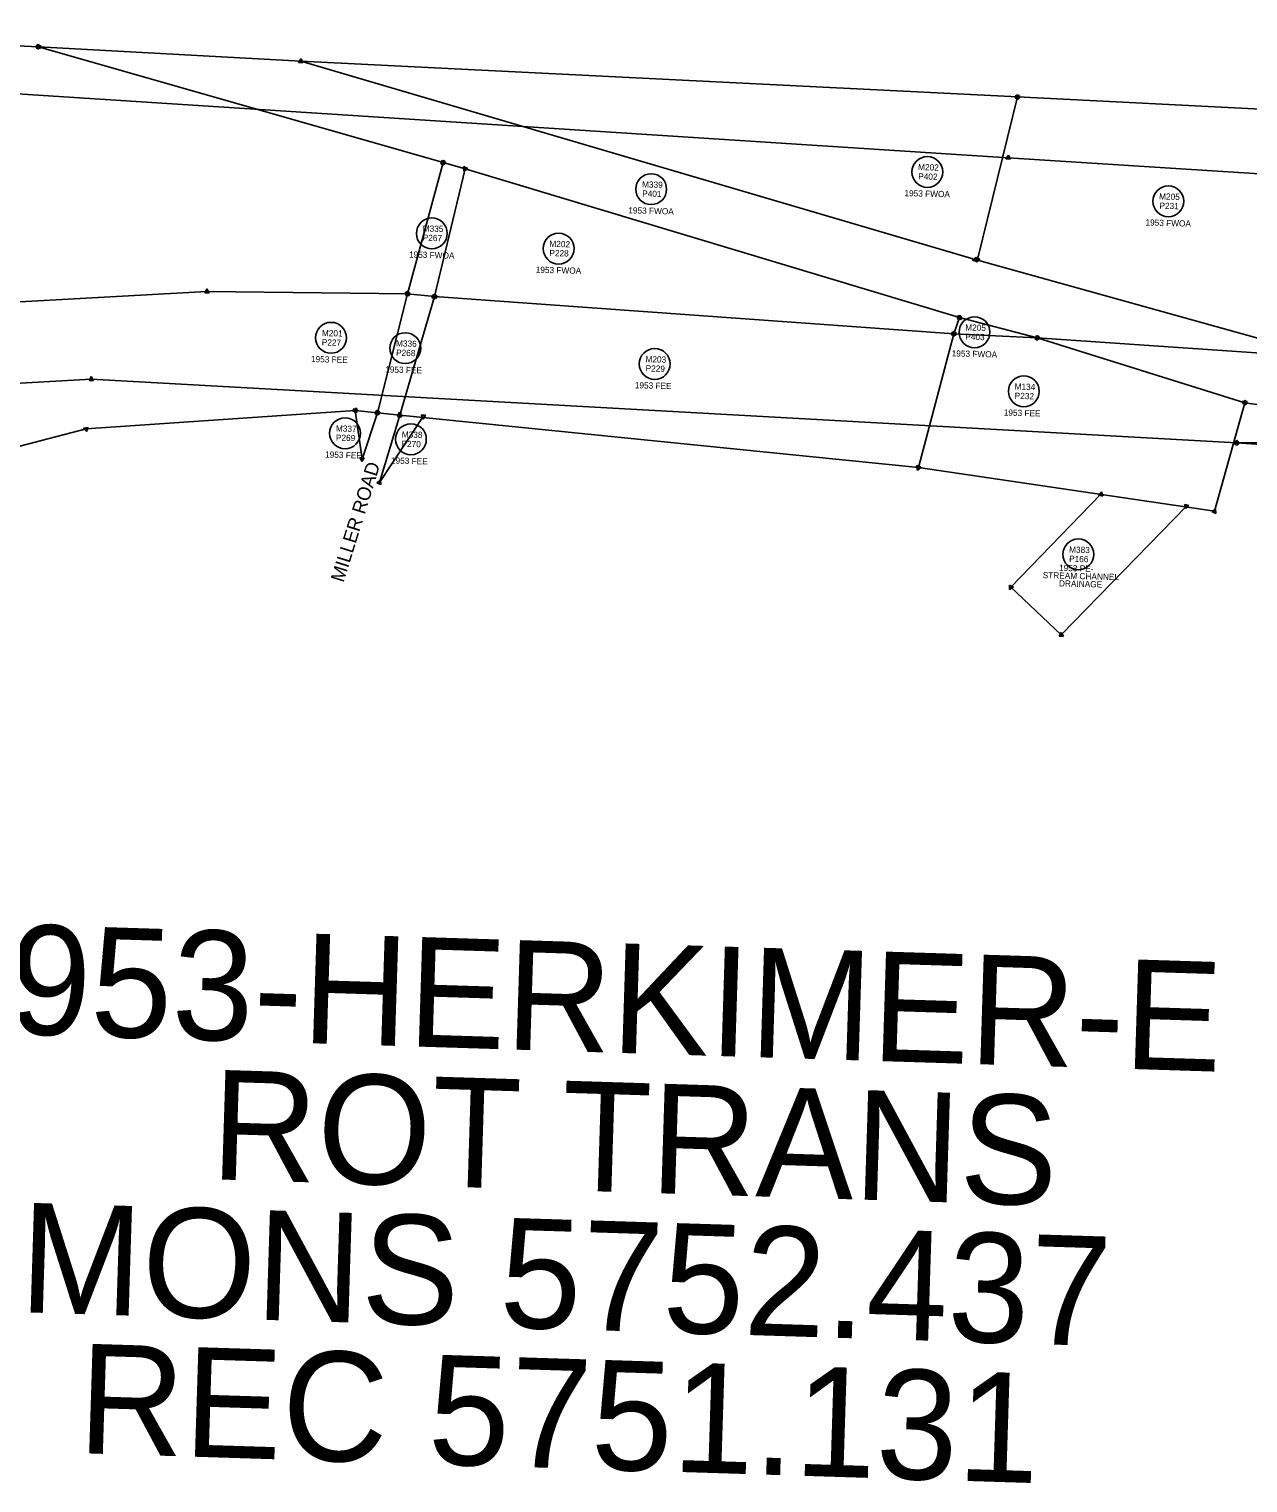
# Model space of a CAD drawing. Extents: x 325018 to 414989, y 1517547 to 1550415.
# Drawn here: x 374498 to 375532, y 1522317 to 1523550 of the extents above; entities that cross this region are included whole.
import ezdxf

# ---------------------------------------------------------------- set-up
doc = ezdxf.new("R2010")
doc.units = 0
for name, color, linetype in [('LAM_I', 7, 'Continuous'), ('Level 56', 7, 'Continuous'), ('MEE', 7, 'Continuous'), ('MHB', 7, 'Continuous'), ('MHBWOA', 7, 'Continuous'), ('MRBL1', 7, 'Continuous'), ('MRBL2', 7, 'Continuous'), ('S_C', 7, 'Continuous')]:
    doc.layers.add(name, color=color, linetype=linetype)

msp = doc.modelspace()

# ---------------------------------------------------------------- linework, layer by layer
at = {"layer": 'Level 56'}
for centre in [(375260.2, 1523429.2), (375025.8, 1523414.6), (375464.8, 1523404.3), (374839.6, 1523377.1), (374947.2, 1523364.2), (374754, 1523288.5), (375300.2, 1523293.2), (374817, 1523279.7), (375028.8, 1523266.3), (375342.1, 1523243.1), (374765.9, 1523207.5), (374821.8, 1523202.4), (375388.4, 1523104.7)]:
    msp.add_circle(centre, 13.1, dxfattribs=at)
at = {"layer": 'MEE'}
for p, q in [((375407.6, 1523155.7), (375331.1, 1523076.8)), ((375373.9, 1523036.3), (375480.1, 1523145.6)), ((375331.1, 1523076.8), (375373.9, 1523036.3))]:
    msp.add_line(p, q, dxfattribs=at)
for points in [[(375405.5, 1523155.1), (375408.1, 1523157.8)], [(375409.1, 1523154.1), (375405.5, 1523155.1)], [(375408.1, 1523157.8), (375409.1, 1523154.1)], [(375479.6, 1523143.5), (375478.6, 1523147.1)], [(375478.6, 1523147.1), (375482.2, 1523146.2)], [(375482.2, 1523146.2), (375479.6, 1523143.5)], [(375329.9, 1523078.6), (375333.2, 1523076.8)], [(375330, 1523074.9), (375329.9, 1523078.6)], [(375333.2, 1523076.8), (375330, 1523074.9)], [(375372, 1523035.2), (375373.8, 1523038.5)], [(375375.8, 1523035.3), (375372, 1523035.2)], [(375373.8, 1523038.5), (375375.8, 1523035.3)]]:
    msp.add_lwpolyline(points, dxfattribs=at)
for centre, radius in [((375407.6, 1523155.7), 1.09), ((375480.1, 1523145.6), 1.09), ((375331.1, 1523076.8), 0.227), ((375373.9, 1523036.3), 0.227)]:
    msp.add_circle(centre, radius, dxfattribs=at)
at = {"layer": 'MHB'}
for p, q in [((374489.7, 1523319), (374648.6, 1523327.8)), ((374818.8, 1523325.8), (374793.5, 1523224.9)), ((374841.7, 1523323.4), (374812.4, 1523222.8)), ((375282.6, 1523291.9), (375353.5, 1523288.4)), ((375353.5, 1523288.4), (375529.7, 1523233.4)), ((374774.5, 1523226.9), (374546, 1523211.1)), ((374793.5, 1523224.9), (374774.5, 1523226.9)), ((374780.3, 1523185.6), (374774.5, 1523226.9)), ((375529.7, 1523233.4), (375503.9, 1523141.3)), ((375529.7, 1523233.4), (375838.3, 1523188.6)), ((374793.5, 1523224.9), (374780.3, 1523185.6)), ((374812.4, 1523222.8), (374793.5, 1523224.9)), ((374812.4, 1523222.8), (374795.2, 1523165.7)), ((374795.2, 1523165.7), (374832.3, 1523221.7)), ((374546, 1523211.1), (374333.7, 1523156.4)), ((375835.5, 1523177.6), (375522.7, 1523199.3)), ((375503.9, 1523141.3), (375252.6, 1523178.3))]:
    msp.add_line(p, q, dxfattribs=at)
for points in [[(374646.8, 1523326.7), (374648.6, 1523330)], [(374650.5, 1523326.7), (374646.8, 1523326.7)], [(374648.6, 1523330), (374650.5, 1523326.7)], [(374816.8, 1523326.7), (374820.6, 1523327.2)], [(374819.1, 1523323.7), (374816.8, 1523326.7)], [(374816.9, 1523325), (374819.1, 1523328)], [(374820.6, 1523324.5), (374816.9, 1523325)], [(374819.1, 1523328), (374820.6, 1523324.5)], [(374820.6, 1523327.2), (374819.1, 1523323.7)], [(374839.8, 1523324.3), (374843.5, 1523324.6)], [(374841.9, 1523321.2), (374839.8, 1523324.3)], [(374843.5, 1523324.6), (374841.9, 1523321.2)], [(375280.7, 1523290.9), (375282.7, 1523294.1)], [(375284.5, 1523290.7), (375280.7, 1523290.9)], [(375282.7, 1523294.1), (375284.5, 1523290.7)], [(375351.5, 1523287.6), (375353.9, 1523290.5)], [(375353.9, 1523290.5), (375355.2, 1523287)], [(375355.2, 1523287), (375351.5, 1523287.6)], [(374772.4, 1523226.6), (374775.4, 1523229)], [(374775.9, 1523225.2), (374772.4, 1523226.6)], [(374774.5, 1523224.8), (374772.7, 1523228.1)], [(374772.7, 1523228.1), (374776.5, 1523228)], [(374776.5, 1523228), (374774.5, 1523224.8)], [(374775.4, 1523229), (374775.9, 1523225.2)], [(374791.3, 1523224.7), (374794.4, 1523226.9)], [(374793.2, 1523222.7), (374791.7, 1523226.2)], [(374791.7, 1523226.2), (374795.5, 1523225.8)], [(374791.8, 1523223.4), (374793, 1523227)], [(374793, 1523227), (374795.5, 1523224.2)], [(374794.4, 1523226.9), (374794.7, 1523223.1)], [(375527.7, 1523232.6), (375530, 1523235.6)], [(375531.4, 1523232.1), (375527.7, 1523232.6)], [(375527.8, 1523234.6), (375531.6, 1523234.5)], [(375529.6, 1523231.2), (375527.8, 1523234.6)], [(375531.6, 1523234.5), (375529.6, 1523231.2)], [(375530, 1523235.6), (375531.4, 1523232.1)], [(374794.7, 1523223.1), (374791.3, 1523224.7)], [(374795.5, 1523224.2), (374791.8, 1523223.4)], [(374795.5, 1523225.8), (374793.2, 1523222.7)], [(374810.2, 1523222.7), (374813.3, 1523224.8)], [(374813.6, 1523221), (374810.2, 1523222.7)], [(374810.8, 1523221.3), (374811.9, 1523225)], [(374814.5, 1523222.2), (374810.8, 1523221.3)], [(374811.9, 1523225), (374814.5, 1523222.2)], [(374813.3, 1523224.8), (374813.6, 1523221)], [(374832.2, 1523219.5), (374830.5, 1523222.9)], [(374830.5, 1523222.9), (374834.3, 1523222.7)], [(374834.3, 1523222.7), (374832.2, 1523219.5)], [(374543.9, 1523211.9), (374547.7, 1523212.5)], [(374546.3, 1523209), (374543.9, 1523211.9)], [(374547.7, 1523212.5), (374546.3, 1523209)], [(375522.6, 1523197.2), (375520.9, 1523200.5)], [(375520.9, 1523200.5), (375524.7, 1523200.3)], [(375524.7, 1523200.3), (375522.6, 1523197.2)], [(374780.1, 1523183.4), (374778.5, 1523186.8)], [(374778.5, 1523186.8), (374782.2, 1523186.5)], [(374782.2, 1523186.5), (374780.1, 1523183.4)], [(375252.3, 1523176.1), (375250.9, 1523179.7)], [(375250.9, 1523179.7), (375254.6, 1523179.1)], [(375254.6, 1523179.1), (375252.3, 1523176.1)], [(374793, 1523165.5), (374796.1, 1523167.7)], [(374796.4, 1523163.9), (374793, 1523165.5)], [(374796.1, 1523167.7), (374796.4, 1523163.9)], [(375501.7, 1523141.2), (375504.9, 1523143.2)], [(375505.1, 1523139.5), (375501.7, 1523141.2)], [(375504.9, 1523143.2), (375505.1, 1523139.5)]]:
    msp.add_lwpolyline(points, dxfattribs=at)
for centre, radius in [((374648.6, 1523327.8), 0.227), ((374818.9, 1523325.8), 1.09), ((374818.8, 1523325.8), 0.227), ((374841.7, 1523323.4), 0.227), ((375282.6, 1523291.9), 1.09), ((375353.5, 1523288.4), 0.227), ((374774.5, 1523226.9), 1.09), ((374774.5, 1523226.9), 0.227), ((375529.7, 1523233.4), 1.09), ((375529.7, 1523233.4), 0.227), ((374793.5, 1523224.9), 1.09), ((374793.5, 1523224.9), 1.09), ((374793.5, 1523224.9), 0.227), ((374812.4, 1523222.8), 1.09), ((374812.4, 1523222.8), 0.227), ((374832.3, 1523221.7), 1.09), ((374546, 1523211.1), 0.227), ((375522.7, 1523199.3), 1.09), ((374780.3, 1523185.6), 0.227), ((375252.6, 1523178.3), 1.09), ((374795.2, 1523165.7), 0.227), ((375503.9, 1523141.3), 0.227)]:
    msp.add_circle(centre, radius, dxfattribs=at)
at = {"layer": 'MHBWOA'}
for p, q in [((374505.7, 1523535.4), (374179, 1523550.5)), ((374505.7, 1523535.4), (374728.3, 1523523.1)), ((374849.1, 1523437.1), (374505.7, 1523535.4)), ((374728.3, 1523523.1), (375336.7, 1523492.9)), ((374728.3, 1523523.1), (375300.7, 1523354.9)), ((375336.7, 1523492.9), (375302.7, 1523354.8)), ((375336.7, 1523492.9), (375626.3, 1523478.2)), ((374849.1, 1523437.1), (374818.8, 1523325.8)), ((374867.8, 1523431.9), (374849.1, 1523437.1)), ((374841.7, 1523323.4), (374867.8, 1523431.9)), ((375287.5, 1523305.6), (374867.8, 1523431.9)), ((375300.7, 1523354.9), (375568.5, 1523280.5)), ((374648.6, 1523327.8), (374818.8, 1523325.8)), ((374818.8, 1523325.8), (374841.7, 1523323.4)), ((375282.6, 1523291.9), (374841.7, 1523323.4)), ((375287.5, 1523305.6), (375282.6, 1523291.9)), ((375353.5, 1523288.4), (375287.5, 1523305.6)), ((375252.6, 1523178.3), (375282.6, 1523291.9)), ((375602, 1523271.3), (375353.5, 1523288.4)), ((374812.4, 1523222.8), (375252.6, 1523178.3))]:
    msp.add_line(p, q, dxfattribs=at)
for points in [[(374503.7, 1523534.4), (374505.8, 1523537.6)], [(374505.3, 1523533.3), (374504, 1523536.8)], [(374504, 1523536.8), (374507.7, 1523536.2)], [(374505.1, 1523533.3), (374504.2, 1523537)], [(374504.2, 1523537), (374507.8, 1523535.9)], [(374507.8, 1523535.9), (374505.1, 1523533.3)], [(374507.7, 1523536.2), (374505.3, 1523533.3)], [(374505.8, 1523537.6), (374507.5, 1523534.2)], [(374507.5, 1523534.2), (374503.7, 1523534.4)], [(374726.3, 1523522.3), (374728.7, 1523525.2)], [(374730, 1523521.7), (374726.3, 1523522.3)], [(374726.4, 1523522.1), (374728.5, 1523525.2)], [(374728.5, 1523525.2), (374730.2, 1523521.9)], [(374728.7, 1523525.2), (374730, 1523521.7)], [(374730.2, 1523521.9), (374726.4, 1523522.1)], [(375334.7, 1523491.9), (375336.8, 1523495)], [(375334.7, 1523493.7), (375338.4, 1523494.2)], [(375336.9, 1523490.7), (375334.7, 1523493.7)], [(375338.5, 1523491.7), (375334.7, 1523491.9)], [(375336.8, 1523495), (375338.5, 1523491.7)], [(375338.4, 1523494.2), (375336.9, 1523490.7)], [(374846.9, 1523437.1), (374850.2, 1523439)], [(374850.1, 1523435.2), (374846.9, 1523437.1)], [(374847.2, 1523436.1), (374849.1, 1523439.3)], [(374851, 1523436), (374847.2, 1523436.1)], [(374848.5, 1523435), (374847.5, 1523438.7)], [(374847.5, 1523438.7), (374851.2, 1523437.7)], [(374851.2, 1523437.7), (374848.5, 1523435)], [(374849.1, 1523439.3), (374851, 1523436)], [(374850.2, 1523439), (374850.1, 1523435.2)], [(374867.2, 1523429.8), (374866.2, 1523433.5)], [(374866.2, 1523433.5), (374869.9, 1523432.5)], [(374867.2, 1523429.8), (374866.3, 1523433.5)], [(374866.3, 1523433.5), (374869.9, 1523432.4)], [(374866.7, 1523430), (374866.7, 1523433.8)], [(374866.7, 1523433.8), (374870, 1523431.9)], [(374870, 1523431.9), (374866.7, 1523430)], [(374869.9, 1523432.5), (374867.2, 1523429.8)], [(374869.9, 1523432.4), (374867.2, 1523429.8)], [(375298.6, 1523354.4), (375301.3, 1523357)], [(375302.2, 1523353.3), (375298.6, 1523354.4)], [(375301.2, 1523353.2), (375302.1, 1523356.9)], [(375302.1, 1523352.7), (375301.2, 1523356.3)], [(375301.2, 1523356.3), (375304.8, 1523355.3)], [(375304.8, 1523354.3), (375301.2, 1523353.2)], [(375301.3, 1523357), (375302.2, 1523353.3)], [(375302.1, 1523356.9), (375304.8, 1523354.3)], [(375304.8, 1523355.3), (375302.1, 1523352.7)], [(374646.8, 1523326.7), (374648.6, 1523330)], [(374650.5, 1523326.7), (374646.8, 1523326.7)], [(374648.6, 1523330), (374650.5, 1523326.7)], [(374816.9, 1523326.8), (374820.6, 1523327.1)], [(374819, 1523323.7), (374816.9, 1523326.8)], [(374818, 1523323.8), (374817.5, 1523327.6)], [(374817.5, 1523327.6), (374821, 1523326.1)], [(374821, 1523326.1), (374818, 1523323.8)], [(374820.6, 1523327.1), (374819, 1523323.7)], [(374839.7, 1523322.5), (374842, 1523325.5)], [(374840, 1523322.1), (374841.5, 1523325.5)], [(374841.5, 1523325.5), (374843.7, 1523322.5)], [(374842, 1523325.5), (374843.5, 1523322.1)], [(374843.5, 1523322.1), (374839.7, 1523322.5)], [(374841.6, 1523321.2), (374839.9, 1523324.6)], [(374839.9, 1523324.6), (374843.7, 1523324.3)], [(374843.7, 1523322.5), (374840, 1523322.1)], [(374843.7, 1523324.3), (374841.6, 1523321.2)], [(375285.4, 1523305.1), (375288.1, 1523307.8)], [(375285.4, 1523305.1), (375288.1, 1523307.7)], [(375289, 1523304.1), (375285.4, 1523305.1)], [(375289.1, 1523304.1), (375285.4, 1523305.1)], [(375285.9, 1523304.2), (375287.1, 1523307.8)], [(375289.6, 1523304.9), (375285.9, 1523304.2)], [(375286.9, 1523303.5), (375286, 1523307.2)], [(375286, 1523307.2), (375289.6, 1523306.2)], [(375289.6, 1523306.2), (375286.9, 1523303.5)], [(375287.1, 1523307.8), (375289.6, 1523304.9)], [(375288.1, 1523307.8), (375289.1, 1523304.1)], [(375288.1, 1523307.7), (375289, 1523304.1)], [(375280.4, 1523291.8), (375283.6, 1523293.9)], [(375283.8, 1523290.1), (375280.4, 1523291.8)], [(375282.5, 1523289.8), (375280.8, 1523293.1)], [(375280.8, 1523293.1), (375284.6, 1523292.9)], [(375280.9, 1523290.7), (375282.4, 1523294.1)], [(375284.6, 1523291), (375280.9, 1523290.7)], [(375282.4, 1523294.1), (375284.6, 1523291)], [(375284.6, 1523292.9), (375282.5, 1523289.8)], [(375283.6, 1523293.9), (375283.8, 1523290.1)], [(375353.2, 1523286.2), (375351.9, 1523289.7)], [(375351.9, 1523289.7), (375355.6, 1523289.1)], [(375352.2, 1523286.7), (375352.8, 1523290.4)], [(375355.7, 1523288), (375352.2, 1523286.7)], [(375352.8, 1523290.4), (375355.7, 1523288)], [(375355.6, 1523289.1), (375353.2, 1523286.2)], [(374810.4, 1523221.9), (374812.6, 1523225)], [(374814.1, 1523221.5), (374810.4, 1523221.9)], [(374812.6, 1523225), (374814.1, 1523221.5)], [(375251.7, 1523176.3), (375251.3, 1523180.1)], [(375251.3, 1523180.1), (375254.8, 1523178.5)], [(375254.8, 1523178.5), (375251.7, 1523176.3)]]:
    msp.add_lwpolyline(points, dxfattribs=at)
for centre, radius in [((374505.7, 1523535.4), 1.09), ((374505.7, 1523535.4), 1.09), ((374505.7, 1523535.4), 0.227), ((374728.4, 1523523.1), 1.09), ((374728.3, 1523523.1), 0.227), ((375336.7, 1523492.9), 1.09), ((375336.7, 1523492.9), 0.227), ((374849.1, 1523437.1), 0.227), ((374849.1, 1523437.1), 0.227), ((374849.1, 1523437.1), 0.227), ((374867.8, 1523431.9), 1.09), ((374867.8, 1523431.9), 0.227), ((374867.8, 1523431.9), 0.227), ((375300.7, 1523354.9), 0.227), ((375302.7, 1523354.8), 1.09), ((375302.7, 1523354.8), 1.09), ((374648.6, 1523327.8), 0.227), ((374818.8, 1523325.8), 0.227), ((374818.8, 1523325.8), 0.227), ((374841.7, 1523323.4), 1.09), ((374841.7, 1523323.4), 1.09), ((374841.7, 1523323.4), 0.227), ((375287.5, 1523305.6), 1.09), ((375287.5, 1523305.6), 1.09), ((375287.5, 1523305.6), 1.09), ((375287.5, 1523305.6), 0.227), ((375282.6, 1523291.9), 1.09), ((375282.6, 1523291.9), 0.227), ((375282.6, 1523291.9), 0.227), ((375353.5, 1523288.4), 0.227), ((375353.5, 1523288.4), 0.227), ((374812.4, 1523222.8), 1.09), ((375252.6, 1523178.3), 0.227)]:
    msp.add_circle(centre, radius, dxfattribs=at)
at = {"layer": 'MRBL1'}
for p, q in [((374372, 1523502.9), (375328.9, 1523441.3)), ((375328.9, 1523441.3), (375704.9, 1523417))]:
    msp.add_line(p, q, dxfattribs=at)
for points in [[(375326.9, 1523440.3), (375329, 1523443.4)], [(375330.7, 1523440.1), (375326.9, 1523440.3)], [(375329, 1523443.4), (375330.7, 1523440.1)]]:
    msp.add_lwpolyline(points, dxfattribs=at)
msp.add_circle((375328.9, 1523441.3), 0.227, dxfattribs=at)
at = {"layer": 'MRBL2'}
for p, q in [((374126.4, 1523230.1), (374550.5, 1523253.4)), ((374550.5, 1523253.4), (375522.7, 1523199.3)), ((375522.7, 1523199.3), (376086.2, 1523207))]:
    msp.add_line(p, q, dxfattribs=at)
for points in [[(374548.6, 1523252.3), (374550.5, 1523255.6)], [(374552.4, 1523252.3), (374548.6, 1523252.3)], [(374550.5, 1523255.6), (374552.4, 1523252.3)], [(375520.8, 1523198.3), (375522.8, 1523201.5)], [(375522.8, 1523201.5), (375524.6, 1523198.2)], [(375524.6, 1523198.2), (375520.8, 1523198.3)]]:
    msp.add_lwpolyline(points, dxfattribs=at)
for centre in [(374550.5, 1523253.4), (375522.7, 1523199.3)]:
    msp.add_circle(centre, 0.227, dxfattribs=at)

# ---------------------------------------------------------------- texts
at = {"layer": 'LAM_I'}
msp.add_text('MILLER ROAD', height=11.626, rotation=72.7464, dxfattribs=at).set_placement((374764.6, 1523080.3))
at = {"layer": 'Level 56'}
for s, height, p in [('M202', 5.25, (375252.3, 1523430.8)), ('P402', 5.25, (375252.4, 1523422.9)), ('M339', 5.25, (375018, 1523416.1)), ('P401', 5.25, (375018.1, 1523408.3)), ('1953 FWOA', 5.25, (375240.7, 1523408.7)), ('M205', 5.25, (375456.9, 1523405.9)), ('1953 FWOA', 5.25, (375006.3, 1523394.1)), ('P231', 5.25, (375457.2, 1523398)), ('1953 FWOA', 5.25, (375445.3, 1523383.8)), ('M335', 5.25, (374831.8, 1523378.7)), ('P267', 5.25, (374831.8, 1523370.8)), ('1953 FWOA', 5.25, (374820.1, 1523356.6)), ('M202', 5.25, (374939.3, 1523365.7)), ('P228', 5.25, (374939.3, 1523357.9)), ('1953 FWOA', 5.25, (374927.7, 1523343.7)), ('M201', 5.25, (374746.2, 1523290)), ('M205', 5.25, (375292.3, 1523294.7)), ('P403', 5.25, (375292.4, 1523286.9)), ('P227', 5.25, (374746.1, 1523282.1)), ('M336', 5.25, (374809.1, 1523281.2)), ('P268', 5.25, (374809.2, 1523273.3)), ('1953 FWOA', 5.25, (375280.8, 1523272.7)), ('1953 FEE', 5.25, (374736.9, 1523267.9)), ('1953 FEE', 5.25, (374799.9, 1523259.1)), ('M203', 5.25, (375020.9, 1523267.8)), ('P229', 5.25, (375021, 1523260)), ('1953 FEE', 5.25, (375011.8, 1523245.7)), ('M134', 5.25, (375334.2, 1523244.6)), ('P232', 5.25, (375334.3, 1523236.7)), ('1953 FEE', 5.25, (375325, 1523222.5)), ('M337', 5.25, (374758.1, 1523209)), ('P269', 5.25, (374758.1, 1523201.2)), ('M338', 5.25, (374814, 1523203.9)), ('1953 FEE', 5.25, (374748.9, 1523186.9)), ('P270', 5.25, (374813.8, 1523196)), ('1953 FEE', 5.25, (374804.8, 1523181.8)), ('P166', 5.25, (375380.5, 1523098.4)), ('M383', 5.25, (375380.5, 1523106.2)), ('1953 PE-', 5.25, (375371.9, 1523090.7)), ('STREAM CHANNEL', 5.249, (375358.1, 1523084.5)), ('DRAINAGE', 5.25, (375371.9, 1523077.5))]:
    msp.add_text(s, height=height, rotation=358.5076, dxfattribs=at).set_placement(p)
at = {"layer": 'S_C'}
for s, height, p in [('1953-HERKIMER-E', 93.011, (374410.6, 1522700.1)), ('ROT TRANS', 93.01, (374651.3, 1522574.5)), ('MONS 5752.437', 93.011, (374488.8, 1522461.7)), ('REC 5751.131', 93.011, (374538.5, 1522342.1))]:
    msp.add_text(s, height=height, rotation=358.2043, dxfattribs=at).set_placement(p)

doc.saveas('drawing.dxf')
